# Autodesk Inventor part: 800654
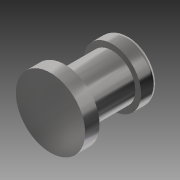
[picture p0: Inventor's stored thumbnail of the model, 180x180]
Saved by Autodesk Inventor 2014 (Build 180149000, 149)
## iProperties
Created: 2007-10
Part Number: 800654
Document SubType Name: Modeling
Designer: AL
Density: 8.08 g/cm^3
Mass: 7.46672 g
Surface Area: 6.63399 cm^2
Volume: 0.924099 cm^3
Material: Stainless Steel
Description: PIVOT PIN
Appearance: Steel - Polished
Component Category: Fasteners
Author: AL
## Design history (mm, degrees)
sketch "Sketch1"
  geometry: L1 (-1.2, 0)-(7.2, 0) reference; L2 (0, -9.381)-(0, 10.089) reference; L3 (0, -6.6)-(6, -6.6); L4 (6, -6.6)-(6, -4.1); L5 (6, -4.1)-(4, -4.1); L6 (4, -4.1)-(4, 4.1); L7 (4, 4.1)-(5, 4.1); L8 (5, 4.1)-(5, 6.1); L9 (4, 7.1)-(0, 7.1); A1 r 1 centre (4, 6.1) between (5, 6.1) and (4, 7.1); 2 further points
  constraints: 14 end point, 5 perpendicular, 3 point on line, 2 parallel, 2 point on circle, 2 tangent, 1 centre point, 1 midpoint
  dimensions: "d1" = 10 diameter of L8 L2; "d2" = 8 diameter of L6 L2; "d3" = 12 diameter of L4 L2; "d4" = 8.2 distance between parallel lines of L7 L5; "d5" = 3 distance between parallel lines of L9 L7; "d6" = 2.5 distance between parallel lines of L3 L5; "d7" = 1 radius of A1
revolve "Revolution1" sketch "Sketch1" stored, may be unused: angle "d8" = 90 deg
body "Solid1"
